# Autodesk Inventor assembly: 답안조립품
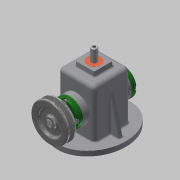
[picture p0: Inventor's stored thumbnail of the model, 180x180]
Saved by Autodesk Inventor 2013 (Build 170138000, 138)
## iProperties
Created: 2017-07
Part Number: 답안조립품
Document SubType Name: Assembly
Designer: Administrator
Author: Administrator
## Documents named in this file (16)
- C:\Users\Administrator\Desktop\470707V1017\답안조립품.iam
- C:\Users\Administrator\Desktop\470707V1017\본체.ipt
- C:\Users\Administrator\Desktop\470707V1017\공용부품\V벨트풀리.ipt
- C:\Users\Administrator\Desktop\470707V1017\공용부품\고정핀 1.2 x  8.ipt
- C:\Users\Administrator\Desktop\470707V1017\공용부품\뒤커버.ipt
- C:\Users\Administrator\Desktop\470707V1017\공용부품\링크.ipt
- C:\Users\Administrator\Desktop\470707V1017\공용부품\멈춤나사 M3x8.ipt
- C:\Users\Administrator\Desktop\470707V1017\공용부품\베어링 12 x 32 x 10.ipt
- C:\Users\Administrator\Desktop\470707V1017\공용부품\볼트 M4 x 12.ipt
- C:\Users\Administrator\Desktop\470707V1017\공용부품\부시.ipt
- C:\Users\Administrator\Desktop\470707V1017\공용부품\슬라이드.ipt
- C:\Users\Administrator\Desktop\470707V1017\공용부품\앞커버.ipt
- C:\Users\Administrator\Desktop\470707V1017\공용부품\오일실 12 25 7.ipt
- C:\Users\Administrator\Desktop\470707V1017\공용부품\키 4 x 4 x 10.ipt
- C:\Users\Administrator\Desktop\470707V1017\공용부품\편심축.ipt
- C:\Users\Administrator\Desktop\470707V1017\공용부품\핀 5 x 18.ipt
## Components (3 placed, 3 different names)
1. V벨트풀리:1
2. 고정핀 1.2 x  8:1
3. 핀 5 x 18:1
